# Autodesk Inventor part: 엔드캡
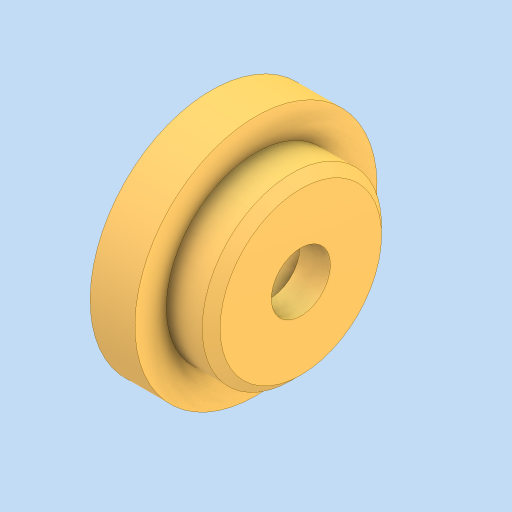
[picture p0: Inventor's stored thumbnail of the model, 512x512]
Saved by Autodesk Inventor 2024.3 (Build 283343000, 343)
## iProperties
Created: 2026-01
Part Number: 엔드캡
Material: 강철, 연강
Document SubType Name: Modeling
Designer: PC2-02
Density: 7.85 g/cm^3
Appearance: 기본값
Author: jhkim
Sending System: Autodesk Inventor 2026
Preprocessor: ST-DEVELOPER v20.1
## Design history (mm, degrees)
node "엔드캡1"
node "솔리드2"
node "솔리드1"
